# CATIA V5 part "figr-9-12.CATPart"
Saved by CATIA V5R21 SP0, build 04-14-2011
Part number: Part2
Bounding box of the stored display mesh (mm): x -96.75 to 0, y -83.031 to 83.031, z -58.031 to 58.031
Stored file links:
  D:\CATIA V5R21 E-RESOURCES\CATIA-V5R21\catia-v5r21-prt\c09-catia-v5r20-prt\c09-catia-v5r21-figr-9-12.CATPart
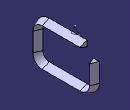
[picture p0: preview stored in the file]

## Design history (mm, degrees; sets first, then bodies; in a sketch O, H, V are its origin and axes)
Body1 (main body)
  Sketch1 on yz-plane, origin (0, 0, 0), H (0, 1, 0), V (0, 0, 1)
    point P1 (-75, 50)
    line L1 (-50, 50) -> (50, 50)
    line L2 (75, 25) -> (75, -25)
    line L3 (50, -50) -> (-50, -50)
    line L4 (-75, -25) -> (-75, 25)
    point P2 (75, 50)
    point P3 (75, -50)
    arc A1 centre (-50, 25) radius 25 from (-50, 50) to (-75, 25) ccw
    arc A2 centre (-50, -25) radius 25 from (-50, -50) to (-75, -25) cw
    arc A3 centre (50, -25) radius 25 from (50, -50) to (75, -25) ccw
    distance V L4 = 75
    distance H L1 = 50
    distance P1 P2 = 150
    radius A1 = 25
    radius A2 = 25
    distance P2 P3 = 100
    radius A3 = 25
    horizontal: L1 H, L3 H
    vertical: L2 V, L4 V
    coincidence: L1 P1, L4 P1, L3 P3, L2 P3, L2 P2, L1 P2
    tangency: A1 L1, A1 L4, A2 L3, A2 L4, A3 L3, A3 L2
  Plane1: type Angle, RefPlane yz-plane, Direction Sketch1.V, Angle 31
  Plane2: type Offset, RefPlane Plane1, Offset -108
  Sketch2 on Plane2, origin (-92.5741, -55.6241, 0), H (-0.515, 0.8572, 0), V (0, 0, 1)
    line L1 (0, 0) -> (-8.0309, -18.5626)
    line L2 (-8.0309, -18.5626) -> (8.1085, -18.5626)
    line L3 (8.1085, -18.5626) -> (0, 0)
    horizontal: L2 H
  Rib1: profile Sketch2, centre curve Sketch1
